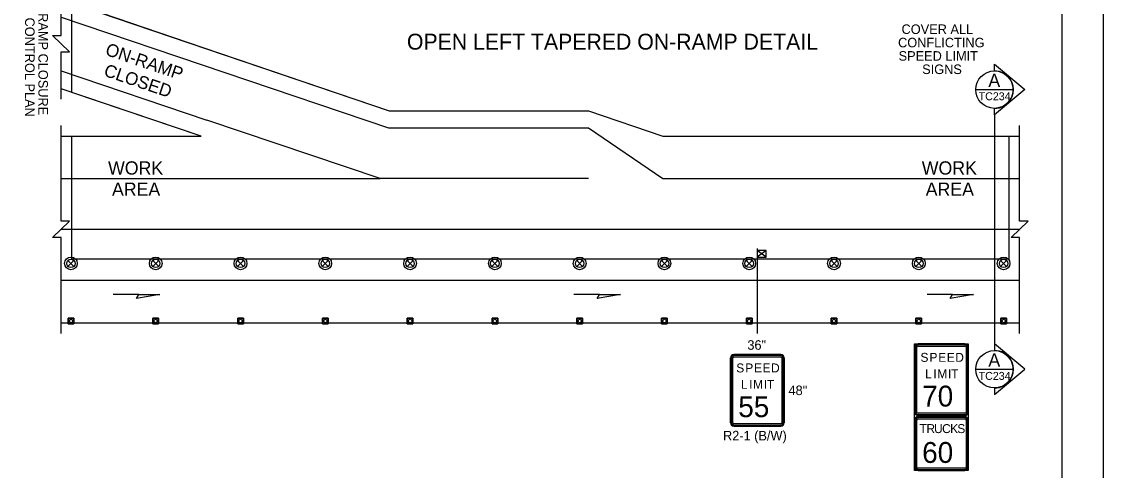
# Model space of a CAD drawing. Extents: x 99999 to 100116, y 99995 to 100013.
# Drawn here: x 100087.9 to 100096.06, y 100002.04 to 100005.42 of the extents above; entities that cross this region are included whole.
import ezdxf

# ---------------------------------------------------------------- set-up
doc = ezdxf.new("R2010")
doc.units = 0
for name, color, linetype in [('Default', 7, 'Continuous'), ('RD_MK_LineEdgeYellow', 7, 'Continuous'), ('RD_MK_LineLane', 7, 'Continuous'), ('SH_DE_DetailHeading2Text', 7, 'Continuous'), ('SH_GI_PlotLimits', 7, 'Continuous'), ('SH_GI_SheetBorder', 7, 'Continuous'), ('SH_TI_WZSectionCut', 7, 'Continuous'), ('TR_SN_ConstructionSigns', 7, 'Continuous'), ('TR_WZ_PortableSignMount5ftMinBlk-Wht', 7, 'Continuous'), ('TR_WZ_TrafficCone', 7, 'Continuous'), ('TR_WZ_TrafficSafetyDrum', 7, 'Continuous'), ('TR_WZ_WorkAreaLabel', 7, 'Continuous'), ('TR_WZ_WorkZoneDetails', 7, 'Continuous')]:
    doc.layers.add(name, color=color, linetype=linetype)

msp = doc.modelspace()

# ---------------------------------------------------------------- linework, layer by layer
at = {"layer": 'Default'}
for p, q in [((100094.638, 100002.4156), (100094.638, 100002.0613)), ((100095.0177, 100002.441), (100094.6633, 100002.441)), ((100095.043, 100002.0613), (100095.043, 100002.4156)), ((100094.6633, 100002.036), (100095.0177, 100002.036))]:
    msp.add_line(p, q, dxfattribs=at)
for centre, start, end in [((100094.6633, 100002.4156), 90, 180), ((100095.0177, 100002.4156), 0, 90), ((100094.6633, 100002.0613), 180, 270.00001), ((100095.0177, 100002.0613), 270.00001, 0.00001)]:
    msp.add_arc(centre, 0.0253, start, end, dxfattribs=at)
at = {"layer": 'RD_MK_LineEdgeYellow'}
for p, q in [((100088.195, 100005.4562), (100090.6655, 100004.622)), ((100088.195, 100005.0509), (100089.2943, 100004.6797)), ((100090.6655, 100004.622), (100092.1758, 100004.622)), ((100092.1758, 100004.622), (100092.7368, 100004.238)), ((100088.195, 100004.238), (100089.2533, 100004.238)), ((100092.7368, 100004.238), (100095.43, 100004.238)), ((100088.195, 100003.47), (100095.43, 100003.47))]:
    msp.add_line(p, q, dxfattribs=at)
at = {"layer": 'RD_MK_LineLane'}
for points in [[(100092.1758, 100004.238), (100090.6024, 100004.238)], [(100095.43, 100003.854), (100088.195, 100003.854)]]:
    msp.add_lwpolyline(points, dxfattribs=at)
at = {"layer": 'SH_GI_PlotLimits'}
msp.add_lwpolyline([(100079.0625, 99999.6875), (100096.0625, 99999.6875), (100096.0625, 100010.6875), (100079.0625, 100010.6875)], close=True, dxfattribs=at)
at = {"layer": 'SH_GI_SheetBorder'}
msp.add_line((100095.75, 100010.375), (100095.75, 100000), dxfattribs=at)
at = {"layer": 'SH_TI_WZSectionCut'}
for p, q in [((100095.2407, 100005.0503), (100095.2407, 100005.1002)), ((100095.2407, 100005.1002), (100095.4688, 100004.9091)), ((100095.4688, 100004.9091), (100095.2407, 100004.718)), ((100095.2407, 100004.718), (100095.2407, 100004.7679)), ((100095.2407, 100004.718), (100095.2407, 100002.99)), ((100095.2407, 100002.99), (100095.2407, 100002.94)), ((100095.4689, 100002.7988), (100095.2407, 100002.99)), ((100095.2407, 100002.6077), (100095.4689, 100002.7988)), ((100095.2407, 100002.6576), (100095.2407, 100002.6077))]:
    msp.add_line(p, q, dxfattribs=at)
for points in [[(100095.0995, 100004.9091), (100095.3819, 100004.9091)], [(100095.0995, 100002.7988), (100095.3819, 100002.7988)]]:
    msp.add_lwpolyline(points, dxfattribs=at)
for centre in [(100095.2407, 100004.9091), (100095.2407, 100002.7988)]:
    msp.add_circle(centre, 0.1412, dxfattribs=at)
for centre in [(100095.2407, 100004.9091), (100095.2407, 100002.7988)]:
    msp.add_arc(centre, 0.1412, 269.99779, 90.00221, dxfattribs=at)
at = {"layer": 'TR_SN_ConstructionSigns'}
for p, q in [((100094.638, 100002.4753), (100094.638, 100002.9646)), ((100094.638, 100002.9646), (100094.638, 100002.4753)), ((100094.6451, 100002.9646), (100094.6451, 100002.4753)), ((100094.6549, 100002.4753), (100094.6549, 100002.9646)), ((100094.6633, 100002.99), (100095.0177, 100002.99)), ((100095.0177, 100002.99), (100094.6633, 100002.99)), ((100095.0177, 100002.9829), (100094.6633, 100002.9829)), ((100094.6633, 100002.9731), (100095.0177, 100002.9731)), ((100095.0261, 100002.9646), (100095.0261, 100002.4753)), ((100095.036, 100002.4753), (100095.036, 100002.9646)), ((100095.043, 100002.9646), (100095.043, 100002.4753)), ((100095.043, 100002.4753), (100095.043, 100002.9646)), ((100093.2475, 100002.3953), (100093.2475, 100002.8846)), ((100093.2475, 100002.8846), (100093.2475, 100002.3953)), ((100093.2546, 100002.8846), (100093.2546, 100002.3953)), ((100093.2644, 100002.3953), (100093.2644, 100002.8846)), ((100093.2728, 100002.91), (100093.6272, 100002.91)), ((100093.6272, 100002.91), (100093.2728, 100002.91)), ((100093.6272, 100002.9029), (100093.2728, 100002.9029)), ((100093.2728, 100002.8931), (100093.6272, 100002.8931)), ((100093.6357, 100002.8846), (100093.6357, 100002.3953)), ((100093.6455, 100002.3953), (100093.6455, 100002.8846)), ((100093.6525, 100002.8846), (100093.6525, 100002.3953)), ((100093.6525, 100002.3953), (100093.6525, 100002.8846)), ((100095.0177, 100002.4668), (100094.6633, 100002.4668)), ((100093.6272, 100002.3868), (100093.2728, 100002.3868)), ((100093.2728, 100002.377), (100093.6272, 100002.377)), ((100094.638, 100002.0613), (100094.638, 100002.4156)), ((100094.638, 100002.4156), (100094.638, 100002.0613)), ((100094.6451, 100002.4156), (100094.6451, 100002.0613)), ((100094.6549, 100002.0613), (100094.6549, 100002.4156)), ((100094.6633, 100002.457), (100095.0177, 100002.457)), ((100095.0177, 100002.45), (100094.6633, 100002.45)), ((100094.6633, 100002.45), (100095.0177, 100002.45)), ((100094.6633, 100002.441), (100095.0177, 100002.441)), ((100095.0177, 100002.441), (100094.6633, 100002.441)), ((100095.0177, 100002.4339), (100094.6633, 100002.4339)), ((100094.6633, 100002.4241), (100095.0177, 100002.4241)), ((100095.0261, 100002.4156), (100095.0261, 100002.0613)), ((100095.036, 100002.0613), (100095.036, 100002.4156)), ((100095.043, 100002.4156), (100095.043, 100002.0613)), ((100095.043, 100002.0613), (100095.043, 100002.4156)), ((100093.6272, 100002.37), (100093.2728, 100002.37)), ((100093.2728, 100002.37), (100093.6272, 100002.37)), ((100095.0177, 100002.0528), (100094.6633, 100002.0528)), ((100094.6633, 100002.043), (100095.0177, 100002.043)), ((100095.0177, 100002.036), (100094.6633, 100002.036)), ((100094.6633, 100002.036), (100095.0177, 100002.036))]:
    msp.add_line(p, q, dxfattribs=at)
msp.add_lwpolyline([(100094.638, 100002.99), (100095.043, 100002.99), (100095.043, 100002.036), (100094.638, 100002.036)], close=True, dxfattribs=at)
for centre, radius, start, end in [((100094.6633, 100002.9646), 0.0253, 90, 180), ((100094.6633, 100002.9646), 0.0253, 90, 180), ((100094.6633, 100002.9646), 0.0183, 90, 180), ((100094.6633, 100002.9646), 0.00844, 90, 180), ((100095.0177, 100002.9646), 0.0253, 0, 90), ((100095.0177, 100002.9646), 0.0253, 360, 90), ((100095.0177, 100002.9646), 0.0183, 0, 90), ((100095.0177, 100002.9646), 0.00844, 360, 90), ((100093.2728, 100002.8846), 0.0253, 90, 180), ((100093.2728, 100002.8846), 0.0253, 90, 180), ((100093.2728, 100002.8846), 0.0183, 90, 180), ((100093.2728, 100002.8846), 0.00844, 90, 180), ((100093.6272, 100002.8846), 0.0253, 360, 90), ((100093.6272, 100002.8846), 0.0253, 360, 90), ((100093.6272, 100002.8846), 0.0183, 0, 90), ((100093.6272, 100002.8846), 0.00844, 360, 90), ((100094.6633, 100002.4753), 0.0253, 180, 270), ((100094.6633, 100002.4753), 0.0253, 180, 270), ((100094.6633, 100002.4753), 0.0183, 180, 270), ((100094.6633, 100002.4753), 0.00844, 180, 270), ((100095.0177, 100002.4753), 0.0253, 270, 0), ((100095.0177, 100002.4753), 0.0183, 270, 360), ((100095.0177, 100002.4753), 0.00844, 270, 0), ((100095.0177, 100002.4753), 0.0253, 270, 0), ((100093.2728, 100002.3953), 0.0253, 180, 270), ((100093.2728, 100002.3953), 0.0253, 180, 270), ((100093.2728, 100002.3953), 0.0183, 180, 270), ((100093.2728, 100002.3953), 0.00844, 180, 270), ((100093.6272, 100002.3953), 0.0253, 270, 360), ((100093.6272, 100002.3953), 0.0183, 270, 360), ((100093.6272, 100002.3953), 0.00844, 270, 0), ((100093.6272, 100002.3953), 0.0253, 270, 360), ((100094.6633, 100002.4156), 0.0253, 90, 180), ((100094.6633, 100002.4156), 0.0253, 90, 180), ((100094.6633, 100002.4156), 0.0183, 90, 180), ((100094.6633, 100002.4156), 0.00844, 90, 180), ((100095.0177, 100002.4156), 0.0253, 0, 90), ((100095.0177, 100002.4156), 0.0253, 360, 90), ((100095.0177, 100002.4156), 0.0183, 0, 90), ((100095.0177, 100002.4156), 0.00844, 360, 90), ((100094.6633, 100002.0613), 0.0253, 180, 270), ((100094.6633, 100002.0613), 0.0253, 180, 270), ((100095.0177, 100002.0613), 0.0253, 270, 0), ((100095.0177, 100002.0613), 0.0253, 270, 0), ((100095.0177, 100002.0613), 0.0183, 270, 360), ((100095.0177, 100002.0613), 0.00844, 270, 0)]:
    msp.add_arc(centre, radius, start, end, dxfattribs=at)
for major_axis, ratio, start_param, end_param in [((-0.0183, 0), 0.999596, 0, 1.570796), ((0.00844, 0), 0.99908, 3.141593, 4.712389)]:
    msp.add_ellipse((100094.6633, 100002.0613), major_axis=major_axis, ratio=ratio, start_param=start_param, end_param=end_param, dxfattribs=at)
at = {"layer": 'TR_WZ_PortableSignMount5ftMinBlk-Wht'}
for p, q in [((100093.45, 100003.71), (100093.45, 100003.63)), ((100093.5167, 100003.644), (100093.45, 100003.696)), ((100093.5167, 100003.696), (100093.45, 100003.644)), ((100093.4834, 100003.67), (100093.4834, 100003.67)), ((100093.4835, 100003.6699), (100093.4835, 100003.6699))]:
    msp.add_line(p, q, dxfattribs=at)
msp.add_lwpolyline([(100093.5167, 100003.644), (100093.5167, 100003.696), (100093.45, 100003.696), (100093.45, 100003.644)], close=True, dxfattribs=at)
at = {"layer": 'TR_WZ_TrafficCone'}
for points in [[(100088.2481, 100003.142), (100088.2907, 100003.142), (100088.2907, 100003.1846), (100088.2481, 100003.1846), (100088.2481, 100003.142)], [(100088.2481, 100003.1846), (100088.2907, 100003.1846), (100088.2907, 100003.142), (100088.2481, 100003.142), (100088.2481, 100003.1846)], [(100088.8881, 100003.142), (100088.9307, 100003.142), (100088.9307, 100003.1846), (100088.8881, 100003.1846), (100088.8881, 100003.142)], [(100088.8881, 100003.1846), (100088.9307, 100003.1846), (100088.9307, 100003.142), (100088.8881, 100003.142), (100088.8881, 100003.1846)], [(100089.5281, 100003.142), (100089.5707, 100003.142), (100089.5707, 100003.1846), (100089.5281, 100003.1846), (100089.5281, 100003.142)], [(100089.5281, 100003.1846), (100089.5707, 100003.1846), (100089.5707, 100003.142), (100089.5281, 100003.142), (100089.5281, 100003.1846)], [(100090.1681, 100003.142), (100090.2107, 100003.142), (100090.2107, 100003.1846), (100090.1681, 100003.1846), (100090.1681, 100003.142)], [(100090.1681, 100003.1846), (100090.2107, 100003.1846), (100090.2107, 100003.142), (100090.1681, 100003.142), (100090.1681, 100003.1846)], [(100090.8081, 100003.142), (100090.8507, 100003.142), (100090.8507, 100003.1846), (100090.8081, 100003.1846), (100090.8081, 100003.142)], [(100090.8081, 100003.1846), (100090.8507, 100003.1846), (100090.8507, 100003.142), (100090.8081, 100003.142), (100090.8081, 100003.1846)], [(100091.4481, 100003.142), (100091.4907, 100003.142), (100091.4907, 100003.1846), (100091.4481, 100003.1846), (100091.4481, 100003.142)], [(100091.4481, 100003.1846), (100091.4907, 100003.1846), (100091.4907, 100003.142), (100091.4481, 100003.142), (100091.4481, 100003.1846)], [(100092.0881, 100003.142), (100092.1307, 100003.142), (100092.1307, 100003.1846), (100092.0881, 100003.1846), (100092.0881, 100003.142)], [(100092.0881, 100003.1846), (100092.1307, 100003.1846), (100092.1307, 100003.142), (100092.0881, 100003.142), (100092.0881, 100003.1846)], [(100092.7281, 100003.142), (100092.7707, 100003.142), (100092.7707, 100003.1846), (100092.7281, 100003.1846), (100092.7281, 100003.142)], [(100092.7281, 100003.1846), (100092.7707, 100003.1846), (100092.7707, 100003.142), (100092.7281, 100003.142), (100092.7281, 100003.1846)], [(100093.3681, 100003.142), (100093.4107, 100003.142), (100093.4107, 100003.1846), (100093.3681, 100003.1846), (100093.3681, 100003.142)], [(100093.3681, 100003.1846), (100093.4107, 100003.1846), (100093.4107, 100003.142), (100093.3681, 100003.142), (100093.3681, 100003.1846)], [(100094.0081, 100003.142), (100094.0507, 100003.142), (100094.0507, 100003.1846), (100094.0081, 100003.1846), (100094.0081, 100003.142)], [(100094.0081, 100003.1846), (100094.0507, 100003.1846), (100094.0507, 100003.142), (100094.0081, 100003.142), (100094.0081, 100003.1846)], [(100094.6481, 100003.142), (100094.6907, 100003.142), (100094.6907, 100003.1846), (100094.6481, 100003.1846), (100094.6481, 100003.142)], [(100094.6481, 100003.1846), (100094.6907, 100003.1846), (100094.6907, 100003.142), (100094.6481, 100003.142), (100094.6481, 100003.1846)], [(100095.2881, 100003.142), (100095.3307, 100003.142), (100095.3307, 100003.1846), (100095.2881, 100003.1846), (100095.2881, 100003.142)], [(100095.2881, 100003.1846), (100095.3307, 100003.1846), (100095.3307, 100003.142), (100095.2881, 100003.142), (100095.2881, 100003.1846)]]:
    msp.add_lwpolyline(points, dxfattribs=at)
for centre in [(100088.2694, 100003.1633), (100088.9094, 100003.1633), (100089.5494, 100003.1633), (100090.1894, 100003.1633), (100090.8294, 100003.1633), (100091.4694, 100003.1633), (100092.1094, 100003.1633), (100092.7494, 100003.1633), (100093.3894, 100003.1633), (100094.0294, 100003.1633), (100094.6694, 100003.1633), (100095.3094, 100003.1633)]:
    msp.add_circle(centre, 0.0133, dxfattribs=at)
at = {"layer": 'TR_WZ_TrafficSafetyDrum'}
for p, q in [((100088.2468, 100003.5753), (100088.292, 100003.6206)), ((100088.292, 100003.5753), (100088.2468, 100003.6206)), ((100088.8868, 100003.5753), (100088.932, 100003.6206)), ((100088.932, 100003.5753), (100088.8868, 100003.6206)), ((100089.5268, 100003.5753), (100089.572, 100003.6206)), ((100089.572, 100003.5753), (100089.5268, 100003.6206)), ((100090.1668, 100003.5753), (100090.212, 100003.6206)), ((100090.212, 100003.5753), (100090.1668, 100003.6206)), ((100090.8068, 100003.5753), (100090.852, 100003.6206)), ((100090.852, 100003.5753), (100090.8068, 100003.6206)), ((100091.4468, 100003.5753), (100091.492, 100003.6206)), ((100091.492, 100003.5753), (100091.4468, 100003.6206)), ((100092.0868, 100003.5753), (100092.132, 100003.6206)), ((100092.132, 100003.5753), (100092.0868, 100003.6206)), ((100092.7268, 100003.5753), (100092.772, 100003.6206)), ((100092.772, 100003.5753), (100092.7268, 100003.6206)), ((100093.3668, 100003.5753), (100093.412, 100003.6206)), ((100093.412, 100003.5753), (100093.3668, 100003.6206)), ((100094.0068, 100003.5753), (100094.052, 100003.6206)), ((100094.052, 100003.5753), (100094.0068, 100003.6206)), ((100094.6468, 100003.5753), (100094.692, 100003.6206)), ((100094.692, 100003.5753), (100094.6468, 100003.6206)), ((100095.2868, 100003.5753), (100095.332, 100003.6206)), ((100095.332, 100003.5753), (100095.2868, 100003.6206))]:
    msp.add_line(p, q, dxfattribs=at)
for centre, radius in [((100088.2694, 100003.598), 0.048), ((100088.2694, 100003.598), 0.048), ((100088.2694, 100003.598), 0.032), ((100088.9094, 100003.598), 0.048), ((100088.9094, 100003.598), 0.048), ((100088.9094, 100003.598), 0.032), ((100089.5494, 100003.598), 0.048), ((100089.5494, 100003.598), 0.048), ((100089.5494, 100003.598), 0.032), ((100090.1894, 100003.598), 0.048), ((100090.1894, 100003.598), 0.048), ((100090.1894, 100003.598), 0.032), ((100090.8294, 100003.598), 0.048), ((100090.8294, 100003.598), 0.048), ((100090.8294, 100003.598), 0.032), ((100091.4694, 100003.598), 0.048), ((100091.4694, 100003.598), 0.048), ((100091.4694, 100003.598), 0.032), ((100092.1094, 100003.598), 0.048), ((100092.1094, 100003.598), 0.048), ((100092.1094, 100003.598), 0.032), ((100092.7494, 100003.598), 0.048), ((100092.7494, 100003.598), 0.048), ((100092.7494, 100003.598), 0.032), ((100093.3894, 100003.598), 0.048), ((100093.3894, 100003.598), 0.048), ((100093.3894, 100003.598), 0.032), ((100094.0294, 100003.598), 0.048), ((100094.0294, 100003.598), 0.048), ((100094.0294, 100003.598), 0.032), ((100094.6694, 100003.598), 0.048), ((100094.6694, 100003.598), 0.048), ((100094.6694, 100003.598), 0.032), ((100095.3094, 100003.598), 0.048), ((100095.3094, 100003.598), 0.048), ((100095.3094, 100003.598), 0.032)]:
    msp.add_circle(centre, radius, dxfattribs=at)
at = {"layer": 'TR_WZ_WorkZoneDetails'}
for p, q in [((100088.195, 100005.5914), (100090.6703, 100004.75)), ((100089.2533, 100004.558), (100088.195, 100004.915)), ((100090.6703, 100004.75), (100092.1758, 100004.75)), ((100092.1758, 100004.75), (100092.7368, 100004.558)), ((100090.6024, 100004.238), (100089.2943, 100004.6797)), ((100088.195, 100004.558), (100089.2533, 100004.558)), ((100092.7368, 100004.558), (100095.43, 100004.558)), ((100089.2533, 100004.238), (100090.6024, 100004.238)), ((100093.45, 100003.63), (100093.45, 100003.07)), ((100088.782, 100003.3639), (100088.5891, 100003.3639)), ((100092.2594, 100003.3639), (100092.0665, 100003.3639)), ((100094.9242, 100003.3639), (100094.7313, 100003.3639)), ((100088.195, 100003.15), (100095.43, 100003.15))]:
    msp.add_line(p, q, dxfattribs=at)
for points in [[(100088.195, 100004.8378), (100088.195, 100005.1943), (100088.259, 100005.1943), (100088.131, 100005.3182), (100088.195, 100005.3182), (100088.195, 100005.6714)], [(100088.195, 100003.07), (100088.195, 100003.792), (100088.131, 100003.792), (100088.259, 100003.9159), (100088.195, 100003.9159), (100088.195, 100004.638)], [(100095.43, 100003.07), (100095.43, 100003.792), (100095.366, 100003.792), (100095.494, 100003.9159), (100095.43, 100003.9159), (100095.43, 100004.638)]]:
    msp.add_lwpolyline(points, dxfattribs=at)
for points in [[(100088.275, 100003.63), (100088.275, 100004.558), (100089.2533, 100004.558), (100088.275, 100004.8881), (100088.275, 100004.8881), (100088.275, 100004.8881), (100088.275, 100005.5642), (100088.275, 100005.5642), (100088.275, 100005.5642), (100089.2641, 100005.228), (100090.6703, 100004.75), (100092.1758, 100004.75), (100092.7368, 100004.558), (100095.35, 100004.558), (100095.35, 100003.63)], [(100088.9392, 100003.3639), (100088.7641, 100003.333), (100088.782, 100003.3639)], [(100092.4166, 100003.3639), (100092.2415, 100003.333), (100092.2594, 100003.3639)], [(100095.0815, 100003.3639), (100094.9064, 100003.333), (100094.9242, 100003.3639)]]:
    msp.add_lwpolyline(points, close=True, dxfattribs=at)

# ---------------------------------------------------------------- texts
at = {"layer": 'Default'}
for s, height, p in [('S', 0.0675, (100094.6819, 100002.855)), ('P', 0.0675, (100094.7501, 100002.855)), ('E', 0.0675, (100094.8162, 100002.855)), ('E', 0.0675, (100094.8803, 100002.855)), ('D', 0.0675, (100094.9445, 100002.855)), ('L', 0.0675, (100094.717, 100002.7312)), ('I', 0.0675, (100094.7791, 100002.7312)), ('M', 0.0675, (100094.8088, 100002.7312)), ('I', 0.0675, (100094.8898, 100002.7312)), ('T', 0.0675, (100094.9134, 100002.7312)), ('70', 0.1575, (100094.6949, 100002.5175)), ('T', 0.0675, (100094.6751, 100002.3172)), ('R', 0.0675, (100094.7271, 100002.3172)), ('U', 0.0675, (100094.7845, 100002.3172)), ('C', 0.0675, (100094.8452, 100002.3172)), ('K', 0.0675, (100094.906, 100002.3172)), ('S', 0.0675, (100094.96, 100002.3172)), ('60', 0.1575, (100094.6948, 100002.0922))]:
    msp.add_text(s, height=height, dxfattribs=at).set_placement(p)
for s, height, p in [('S', 0.0675, (100093.2914, 100002.775)), ('P', 0.0675, (100093.3596, 100002.775)), ('E', 0.0675, (100093.4257, 100002.775)), ('E', 0.0675, (100093.4899, 100002.775)), ('D', 0.0675, (100093.554, 100002.775)), ('L', 0.0675, (100093.3265, 100002.6512)), ('I', 0.0675, (100093.3886, 100002.6512)), ('M', 0.0675, (100093.4183, 100002.6512)), ('I', 0.0675, (100093.4993, 100002.6512)), ('T', 0.0675, (100093.5229, 100002.6512)), ('55', 0.1575, (100093.3068, 100002.4375))]:
    msp.add_text(s, height=height, rotation=360, dxfattribs=at).set_placement(p)
at = {"layer": 'SH_DE_DetailHeading2Text'}
msp.add_text('OPEN LEFT TAPERED ON-RAMP DETAIL', height=0.12, rotation=360, dxfattribs=at).set_placement((100090.8055, 100005.211))
at = {"layer": 'SH_TI_WZSectionCut'}
for s, height, rotation, p in [('A', 0.1, 0.00995, (100095.1945, 100004.9297)), ('TC234', 0.06, 360, (100095.1214, 100004.8291)), ('A', 0.1, 0.00995, (100095.1945, 100002.8195)), ('TC234', 0.06, 360, (100095.1214, 100002.7188))]:
    msp.add_text(s, height=height, rotation=rotation, dxfattribs=at).set_placement(p)
at = {"layer": 'TR_SN_ConstructionSigns'}
for s, p in [('COVER ALL', (100094.5392, 100005.3291)), ('CONFLICTING', (100094.5128, 100005.2283)), ('SPEED LIMIT', (100094.5168, 100005.1275)), ('SIGNS', (100094.6947, 100005.0267))]:
    msp.add_text(s, height=0.072, dxfattribs=at).set_placement(p)
msp.add_text('36"', height=0.072, rotation=360, dxfattribs=at).set_placement((100093.3753, 100002.946))
at = {"layer": 'TR_WZ_WorkAreaLabel'}
for s, p in [('WORK', (100088.5496, 100004.268)), ('WORK', (100094.6919, 100004.268)), ('AREA', (100088.5793, 100004.108)), ('AREA', (100094.7215, 100004.108))]:
    msp.add_text(s, height=0.1, dxfattribs=at).set_placement(p)
at = {"layer": 'TR_WZ_WorkZoneDetails'}
for s, height, rotation, p in [('TRAFFIC CONTROL PLAN', 0.072, 270, (100087.923, 100005.8862)), ('SEE ON-RAMP CLOSURE', 0.072, 270, (100088.0238, 100005.8822)), ('ON-RAMP', 0.096, 341.34097, (100088.5223, 100005.1734)), ('CLOSED', 0.096, 341.34097, (100088.5108, 100005.0152)), ('48"', 0.072, 360, (100093.6858, 100002.604)), ('R2-1 (B/W)', 0.072, 360, (100093.1913, 100002.262))]:
    msp.add_text(s, height=height, rotation=rotation, dxfattribs=at).set_placement(p)

doc.saveas('drawing.dxf')
